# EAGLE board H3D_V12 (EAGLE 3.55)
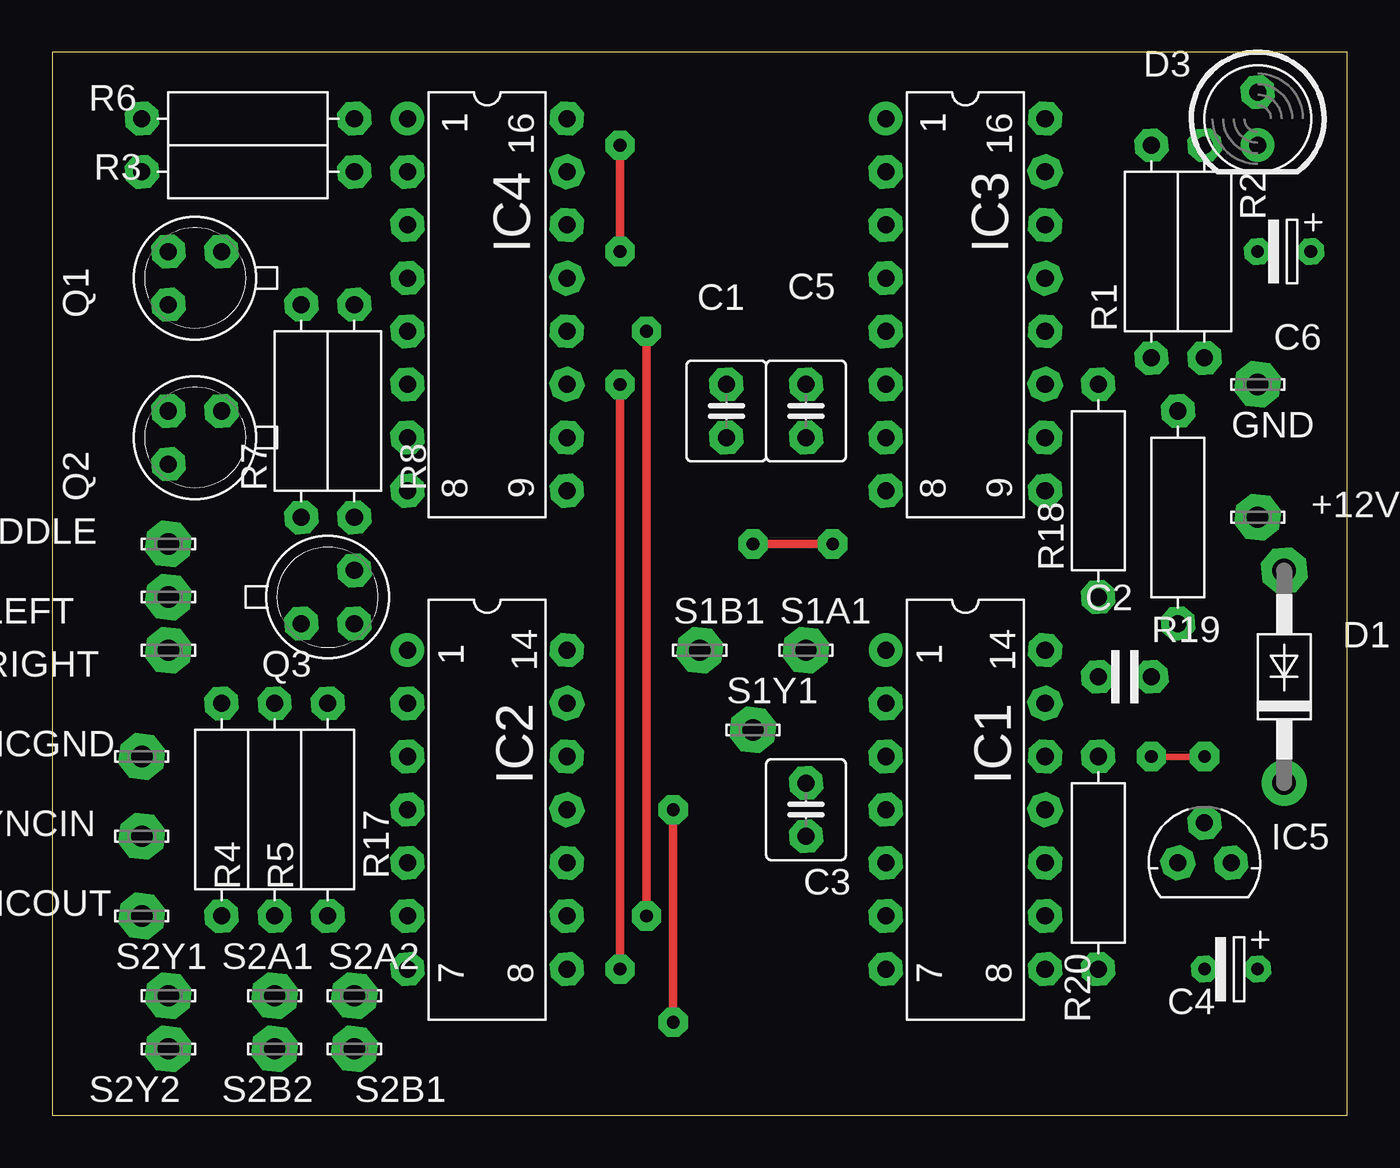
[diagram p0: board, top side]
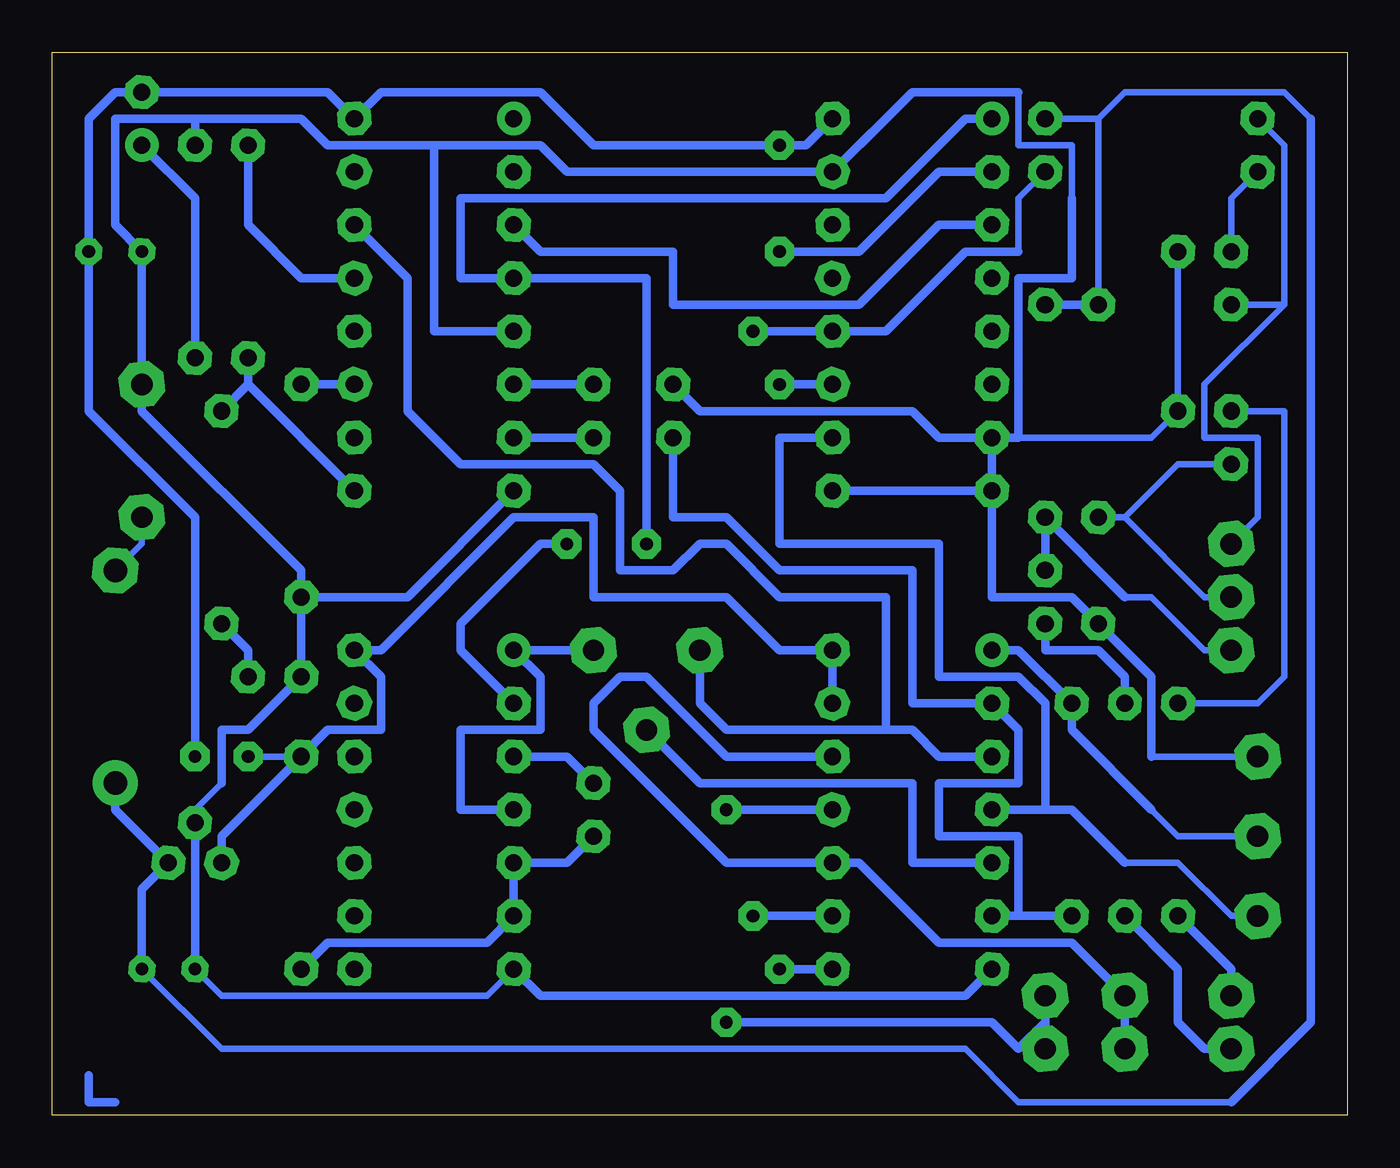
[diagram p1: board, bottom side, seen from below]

Size 61.9 x 50.79 mm. Coordinates in mm from the lower left corner, seen from the top.
Outline: 0,0 61.9,0 61.9,50.79 0,50.79 0,0
Copper layers used: Top, Bottom

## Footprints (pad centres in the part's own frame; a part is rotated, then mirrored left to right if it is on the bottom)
P10 = drill 1.016 pad 2.159 octagon:  0,0
,5-4 = drill 0.813 pad 1.6 octagon:  -1.27,0;  1.27,0
2,5 = drill 0.813 pad 1.6 octagon:  -1.27,0;  1.27,0
-2,5 = drill 0.61 pad 1.27 octagon:  -1.27,0;  1.27,0
41-10 = drill 1.118 pad 2.159 octagon:  5.08,0 | drill 1.118 pad 2.159 round:  -5.08,0
D5 = drill 0.813 pad 1.6 octagon:  -1.27,0 | drill 0.813 pad 1.6 round:  1.27,0
L14 = drill 0.813 pad 1.6 round:  -7.62,-3.81 | drill 0.813 pad 1.6 octagon:  -5.08,-3.81;  7.62,-3.81;  7.62,3.81;  -2.54,-3.81;  0,-3.81;  5.08,-3.81;  2.54,-3.81;  5.08,3.81;  2.54,3.81;  0,3.81;  -2.54,3.81;  -5.08,3.81;  -7.62,3.81
L16 = drill 0.813 pad 1.6 round:  -8.89,-3.81 | drill 0.813 pad 1.6 octagon:  -6.35,-3.81;  6.35,-3.81;  8.89,-3.81;  -3.81,-3.81;  -1.27,-3.81;  3.81,-3.81;  1.27,-3.81;  8.89,3.81;  6.35,3.81;  3.81,3.81;  1.27,3.81;  -1.27,3.81;  -3.81,3.81;  -6.35,3.81;  -8.89,3.81
L16' = drill 0.813 pad 1.6 round:  -8.89,-3.81 | drill 0.813 pad 1.6 octagon:  -6.35,-3.81;  -3.81,-3.81;  -1.27,-3.81;  1.27,-3.81;  3.81,-3.81;  6.35,-3.81;  8.89,-3.81;  8.89,3.81;  6.35,3.81;  3.81,3.81;  1.27,3.81;  -1.27,3.81;  -3.81,3.81;  -6.35,3.81;  -8.89,3.81
LXX = drill 0.813 pad 1.6 octagon:  -1.27,0;  0,1.905;  1.27,0
18 = drill 0.813 pad 1.6 octagon:  -1.27,-1.27;  1.27,-1.27;  1.27,1.27
10 = drill 0.813 pad 1.6 octagon:  -5.08,0;  5.08,0

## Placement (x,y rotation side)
+12V  LSP10  [P10]  57.62,28.57 0 top
C1  100n  [,5-4]  32.22,33.65 270 top
C2  1u  [2,5]  51.27,20.95 0 top
C3  10n  [,5-4]  36.03,14.6 270 top
C4  100u  [-2,5]  56.35,6.98 180 top
C5  30n  [,5-4]  36.03,33.65 90 top
C6  100u  [-2,5]  58.89,41.27 180 top
D1  1N4004  [41-10]  58.89,20.95 90 top
D3  LED gruen  [D5]  57.62,47.62 270 top
GND  LSP10  [P10]  57.62,34.92 0 top
IC1  4001  [L14]  43.65,14.6 270 top
IC2  4030  [L14]  20.79,14.6 270 top
IC3  4046  [L16]  43.65,38.73 270 top
IC4  4520  [L16']  20.79,38.73 270 top
IC5  78L05  [LXX]  55.08,12.06 0 top
LEFT  LSP10  [P10]  5.55,24.76 0 top
MIDDLE  LSP10  [P10]  5.55,27.3 0 top
Q1  2N2222  [18]  6.82,40 180 top
Q2  2N2222  [18]  6.82,32.38 180 top
Q3  2N2222  [18]  13.17,24.76 0 top
R1  100k  [10]  52.54,41.27 90 top
R2  1.5k  [10]  55.08,41.27 270 top
R3  10k  [10]  9.36,45.08 180 top
R4  10k  [10]  8.09,14.6 90 top
R5  10k  [10]  10.63,14.6 90 top
R6  1.5k  [10]  9.36,47.62 0 top
R7  1.5k  [10]  11.9,33.65 90 top
R8  1.5k  [10]  14.44,33.65 90 top
R17  100k  [10]  13.17,14.6 270 top
R18  100k  [10]  50,29.84 90 top
R19  10k  [10]  53.81,28.57 90 top
R20  10k  [10]  50,12.06 90 top
RIGHT  LSP10  [P10]  5.55,22.22 0 top
S1A1  LSP10  [P10]  36.03,22.22 0 top
S1B1  LSP10  [P10]  30.95,22.22 0 top
S1Y1  LSP10  [P10]  33.49,18.41 0 top
S2A1  LSP10  [P10]  10.63,5.71 0 top
S2A2  LSP10  [P10]  14.44,5.71 0 top
S2B1  LSP10  [P10]  14.44,3.17 0 top
S2B2  LSP10  [P10]  10.63,3.17 0 top
S2Y1  LSP10  [P10]  5.55,5.71 0 top
S2Y2  LSP10  [P10]  5.55,3.17 0 top
VSYNCGND  LSP10  [P10]  4.28,17.14 0 top
VSYNCIN  LSP10  [P10]  4.28,13.33 0 top
VSYNCOUT  LSP10  [P10]  4.28,9.52 0 top

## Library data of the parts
+12V GND LEFT MIDDLE RIGHT S1A1 S1B1 S1Y1 S2A1 S2A2 S2B1 S2B2 S2Y1 S2Y2 VSYNCGND VSYNCIN VSYNCOUT = SOLPAD
C1 C3 C5 = CAP
C2 C4 C6 R1-R8 R17-R20 = DISCRETE
D1 = DIODE
D3 = LED
IC1-IC3 = 40XX
IC4 = 45XX
IC5 = V-REG
Q1-Q3 = NPN

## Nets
+5V: C6. D3. IC1. IC2. IC3. IC4. IC5. R20.
+12V: C4. D1. IC5. R6. R7. R8.
GND: C1. C2. C4. C6. GND. IC1. IC2. IC3. IC4. IC5. Q1. Q2. Q3. R2. R18. VSYNCGND.
N$1: IC2. R17. VSYNCIN.
N$2: IC2. IC4. VSYNCOUT.
N$3: IC3. R18.
N$4: IC3. R1.
N$5: R4. S2Y1.
N$6: +12V. D1.
N$7: C5. IC3.
N$8: D3. R2.
N$9: IC2. IC3. S1B1.
N$10: IC2. S2A1. S2B2.
N$11: C3. IC1.
N$12: C3. IC1. R20.
N$14: IC1. S1A1.
N$15: IC1. IC3. IC4.
N$16: C2. R19.
N$17: IC3. R1. R19.
N$18: IC3. IC4.
N$19: C5. IC3.
N$20: Q3. R5.
N$21: Q2. R4.
N$22: Q1. R3.
N$23: C1. IC2. R17.
N$24: R5. S2Y2.
N$25: IC2. IC4.
N$26: IC2. S2A2. S2B1.
N$27: IC2. S1Y1.
N$28: LEFT. Q2. R7.
N$30: IC2. IC4. R3.
N$31: Q3. R8. RIGHT.
N$32: MIDDLE. Q1. R6.

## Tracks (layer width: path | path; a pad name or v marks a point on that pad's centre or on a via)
+5V  (via drill 0.61 pad 1.4)
  Top 0.305: v52.54,17.14 v55.08,17.14
  Top 0.406: v27.14,46.35 v27.14,41.27
  Bottom 0.305: R20. v52.54,17.14
  Bottom 0.406: IC4. 25.87,46.35 v27.14,46.35 36.03,46.35 38.57,48.89 46.19,48.89 IC3. 48.73,48.89 57.62,48.89 58.89,48.89 60.16,47.62 60.16,41.27 60.16,33.65 55.08,28.57 v55.08,17.14 | 16.98,45.08 19.52,45.08 23.33,41.27 v27.14,41.27 | 24.6,19.68 IC2. 27.14,22.22 29.68,24.76 36.03,24.76 36.03,28.57 39.84,28.57 46.19,22.22 IC1. 46.19,20.95 46.19,18.41 48.73,18.41 R20. 53.81,13.33 53.81,12.06
+12V
  Bottom 0.305: 5.55,0.63 15.71,0.63 18.25,3.17 53.81,3.17 57.62,6.98 | 11.9,47.62 R6. | 11.9,47.62 R7. | 1.74,47.62 3.01,48.89 10.63,48.89 11.9,47.62
  Bottom 0.406: R7. R8. | R7. R8. | R7. R8. | 1.74,47.62 1.74,4.44 5.55,0.63 | 57.62,6.98 57.62,10.79 IC5. 58.89,14.6 D1.
GND
  Bottom 0.305: 13.17,43.81 13.17,46.35 15.71,46.35 15.71,48.89 | VSYNCGND. 9.36,17.14 | 15.71,32.38 9.36,32.38 8.09,33.65 8.09,41.27 | 39.84,6.98 41.11,5.71 53.81,5.71 C4. | 55.08,13.96 55.08,14.6 53.81,15.87
  Bottom 0.406: 24.6,45.08 22.06,47.62 | 39.84,37.46 43.65,37.46 43.65,46.35 | 43.65,46.35 38.57,46.35 37.3,45.08 24.6,45.08 | 39.84,29.84 44.92,24.76 50,24.76 | 43.65,46.35 48.73,46.35 50,47.62 55.08,47.62 | 16.98,29.84 24.6,29.84 | 24.6,45.08 20.79,48.89 15.71,48.89 | 9.36,17.14 9.36,20.95 11.9,23.49 13.17,24.76 16.98,24.76 16.98,29.84 | 16.98,29.84 16.98,32.38 | 16.98,32.38 19.52,32.38 20.79,33.65 30.95,33.65 32.22,34.92 | 16.98,32.38 15.71,32.38 15.71,40 13.17,40 13.17,43.81 | 16.98,6.98 18.25,5.71 38.57,5.71 39.84,6.98 | 55.08,47.62 58.89,47.62 58.89,42.54 C6. GND. 57.62,33.65 50,26.03 50,24.76 | 55.08,47.62 55.08,46.35 | 53.81,15.87 53.81,18.41 52.54,18.41 50,20.95 50,24.76 | C4. 55.08,13.96
N$1
  Bottom 0.305: VSYNCIN. 8.09,13.33 9.36,14.6
  Bottom 0.406: 16.98,22.22 15.71,22.22 13.17,19.68 13.17,18.41 9.36,14.6
N$2
  Bottom 0.305: VSYNCOUT. 5.55,9.52 8.09,12.06 10.63,12.06
  Bottom 0.406: 14.44,14.6 16.98,14.6 | 14.44,14.6 14.44,19.68 15.71,20.95 19.52,20.95 19.52,27.3 27.14,27.3 27.14,32.38 24.6,32.38 | 14.44,14.6 13.17,14.6 10.63,12.06
N$3
  Bottom 0.406: 47.46,34.92 R18.
N$4
  Bottom 0.406: 47.46,40 50,40 52.54,42.54 R1.
N$5
  Bottom 0.406: S2Y1. 5.55,6.98 8.09,9.52
N$6
  Bottom 0.305: +12V. 57.62,27.3 58.89,26.03
N$7
  Bottom 0.406: C5. 39.84,34.92
N$8
  Bottom 0.406: R2. 55.08,43.81 D3.
N$9
  Bottom 0.406: 16.98,17.14 19.52,17.14 20.79,18.41 22.06,18.41 | 22.06,18.41 29.68,18.41 30.95,19.68 S1B1. | 47.46,42.54 44.92,40 44.92,33.65 42.38,31.11 36.03,31.11 34.76,29.84 34.76,26.03 32.22,26.03 30.95,27.3 29.68,27.3 27.14,24.76 22.06,24.76 22.06,18.41
N$10
  Bottom 0.406: 24.6,17.14 29.68,17.14 33.49,20.95 34.76,20.95 36.03,19.68 36.03,18.41 29.68,12.06 24.6,12.06 23.33,12.06 19.52,8.25 13.17,8.25 S2A1. S2B2.
N$11
  Bottom 0.406: 39.84,17.14 37.3,17.14 36.03,15.87
N$12
  Bottom 0.406: C3. 37.3,12.06 39.84,12.06 39.84,9.52 41.11,8.25 48.73,8.25 50,6.98
N$14
  Bottom 0.406: S1A1. 39.84,22.22 38.57,20.95 38.57,18.41 42.38,18.41 42.38,14.6 39.84,14.6
N$15  (via drill 0.61 pad 1.4)
  Top 0.406: v37.3,27.3 v33.49,27.3
  Bottom 0.406: 39.84,19.68 42.38,22.22 42.38,23.49 38.57,27.3 v37.3,27.3 | 16.98,47.62 18.25,47.62 22.06,43.81 42.38,43.81 42.38,40 39.84,40 33.49,40 v33.49,27.3
N$16
  Bottom 0.406: 53.81,23.49 52.54,22.22 C2.
N$17
  Bottom 0.406: 47.46,29.84 52.54,34.92 | 52.54,34.92 52.54,36.19 | 52.54,34.92 R19.
N$18
  Bottom 0.406: 16.98,42.54 19.52,42.54 23.33,38.73 32.22,38.73 32.22,41.27 38.57,41.27 39.84,42.54
N$19
  Bottom 0.406: 36.03,32.38 39.84,32.38
N$20
  Bottom 0.406: 14.44,23.49 14.44,22.22 11.9,22.22 10.63,20.95 R5.
N$21
  Bottom 0.305: R4. 6.82,19.68 4.28,19.68 3.01,20.95 3.01,33.65 5.55,33.65
N$22
  Bottom 0.305: 5.55,41.27 5.55,43.81 R3.
N$23
  Bottom 0.406: 15.71,9.52 15.71,13.33 19.52,13.33 19.52,15.87 15.71,15.87 15.71,18.41 16.98,19.68 20.79,19.68 20.79,26.03 27.14,26.03 29.68,28.57 32.22,28.57 C1. | 15.71,9.52 16.98,9.52 | R17. 15.71,9.52
N$24
  Bottom 0.406: S2Y2. 6.82,3.17 8.09,4.44 8.09,6.98 10.63,9.52
N$25  (via drill 0.61 pad 1.4)
  Top 0.406: v27.14,6.98 v27.14,34.92
  Bottom 0.406: 24.6,6.98 v27.14,6.98 | v27.14,34.92 24.6,34.92
N$26  (via drill 0.61 pad 1.4)
  Top 0.406: v29.68,4.44 v29.68,14.6
  Bottom 0.406: v29.68,14.6 24.6,14.6 | S2B1. S2A2. 14.44,4.44 15.71,3.17 16.98,4.44 v29.68,4.44
N$27
  Bottom 0.406: S1Y1. 30.95,15.87 20.79,15.87 20.79,12.06 16.98,12.06
N$28
  Bottom 0.305: 10.63,28.57 11.9,28.57 | 10.63,28.57 8.09,31.11 Q2. | LEFT. 6.82,24.76 10.63,28.57
N$30  (via drill 0.61 pad 1.4)
  Top 0.406: v28.41,9.52 v28.41,37.46
  Bottom 0.305: 15.71,41.27 15.71,43.81 14.44,45.08
  Bottom 0.406: 24.6,9.52 v28.41,9.52 | v28.41,37.46 24.6,37.46 22.06,37.46 18.25,41.27 15.71,41.27
N$31
  Bottom 0.305: RIGHT. 6.82,22.22 9.36,24.76 10.63,24.76
  Bottom 0.406: 10.63,24.76 14.44,28.57 Q3.
N$32
  Bottom 0.305: 3.01,38.73 3.01,46.35 4.28,47.62 | 3.01,38.73 Q1. | MIDDLE. 4.28,28.57 4.28,32.38 6.82,32.38 6.82,34.92 3.01,38.73
N$33
  Bottom 0.406: 58.89,0.63 60.16,0.63 60.16,1.9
